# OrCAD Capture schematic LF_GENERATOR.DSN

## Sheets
1 2. description: size A3
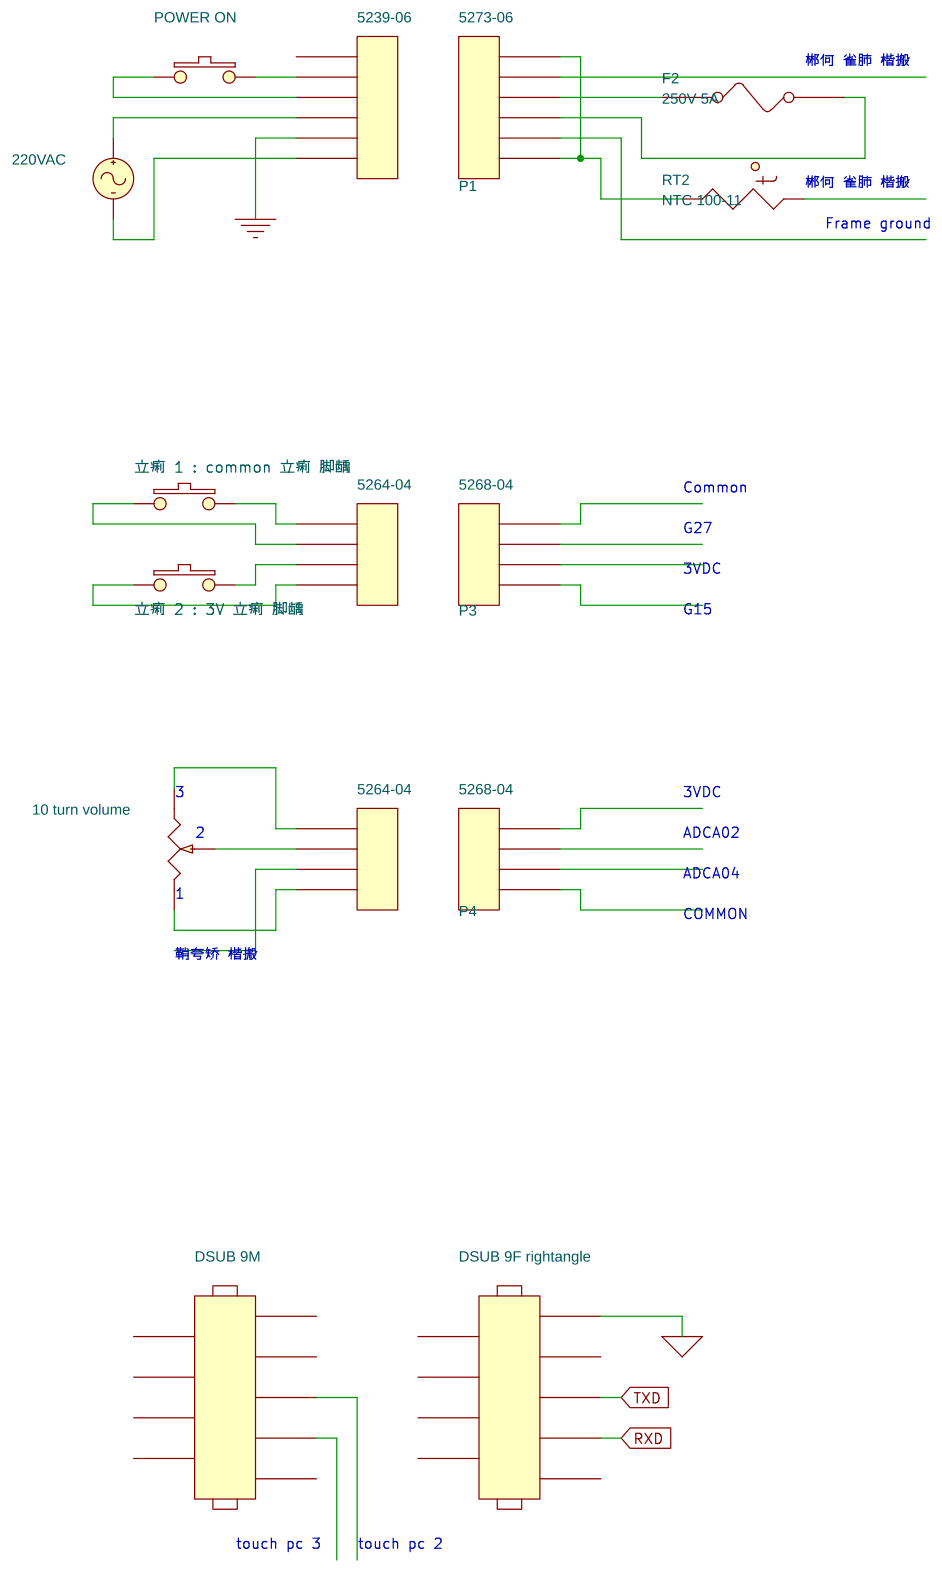
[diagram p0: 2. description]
2 1. Full_Design: size A3; title: LF generator [BELCANTO]; rev: 1.52
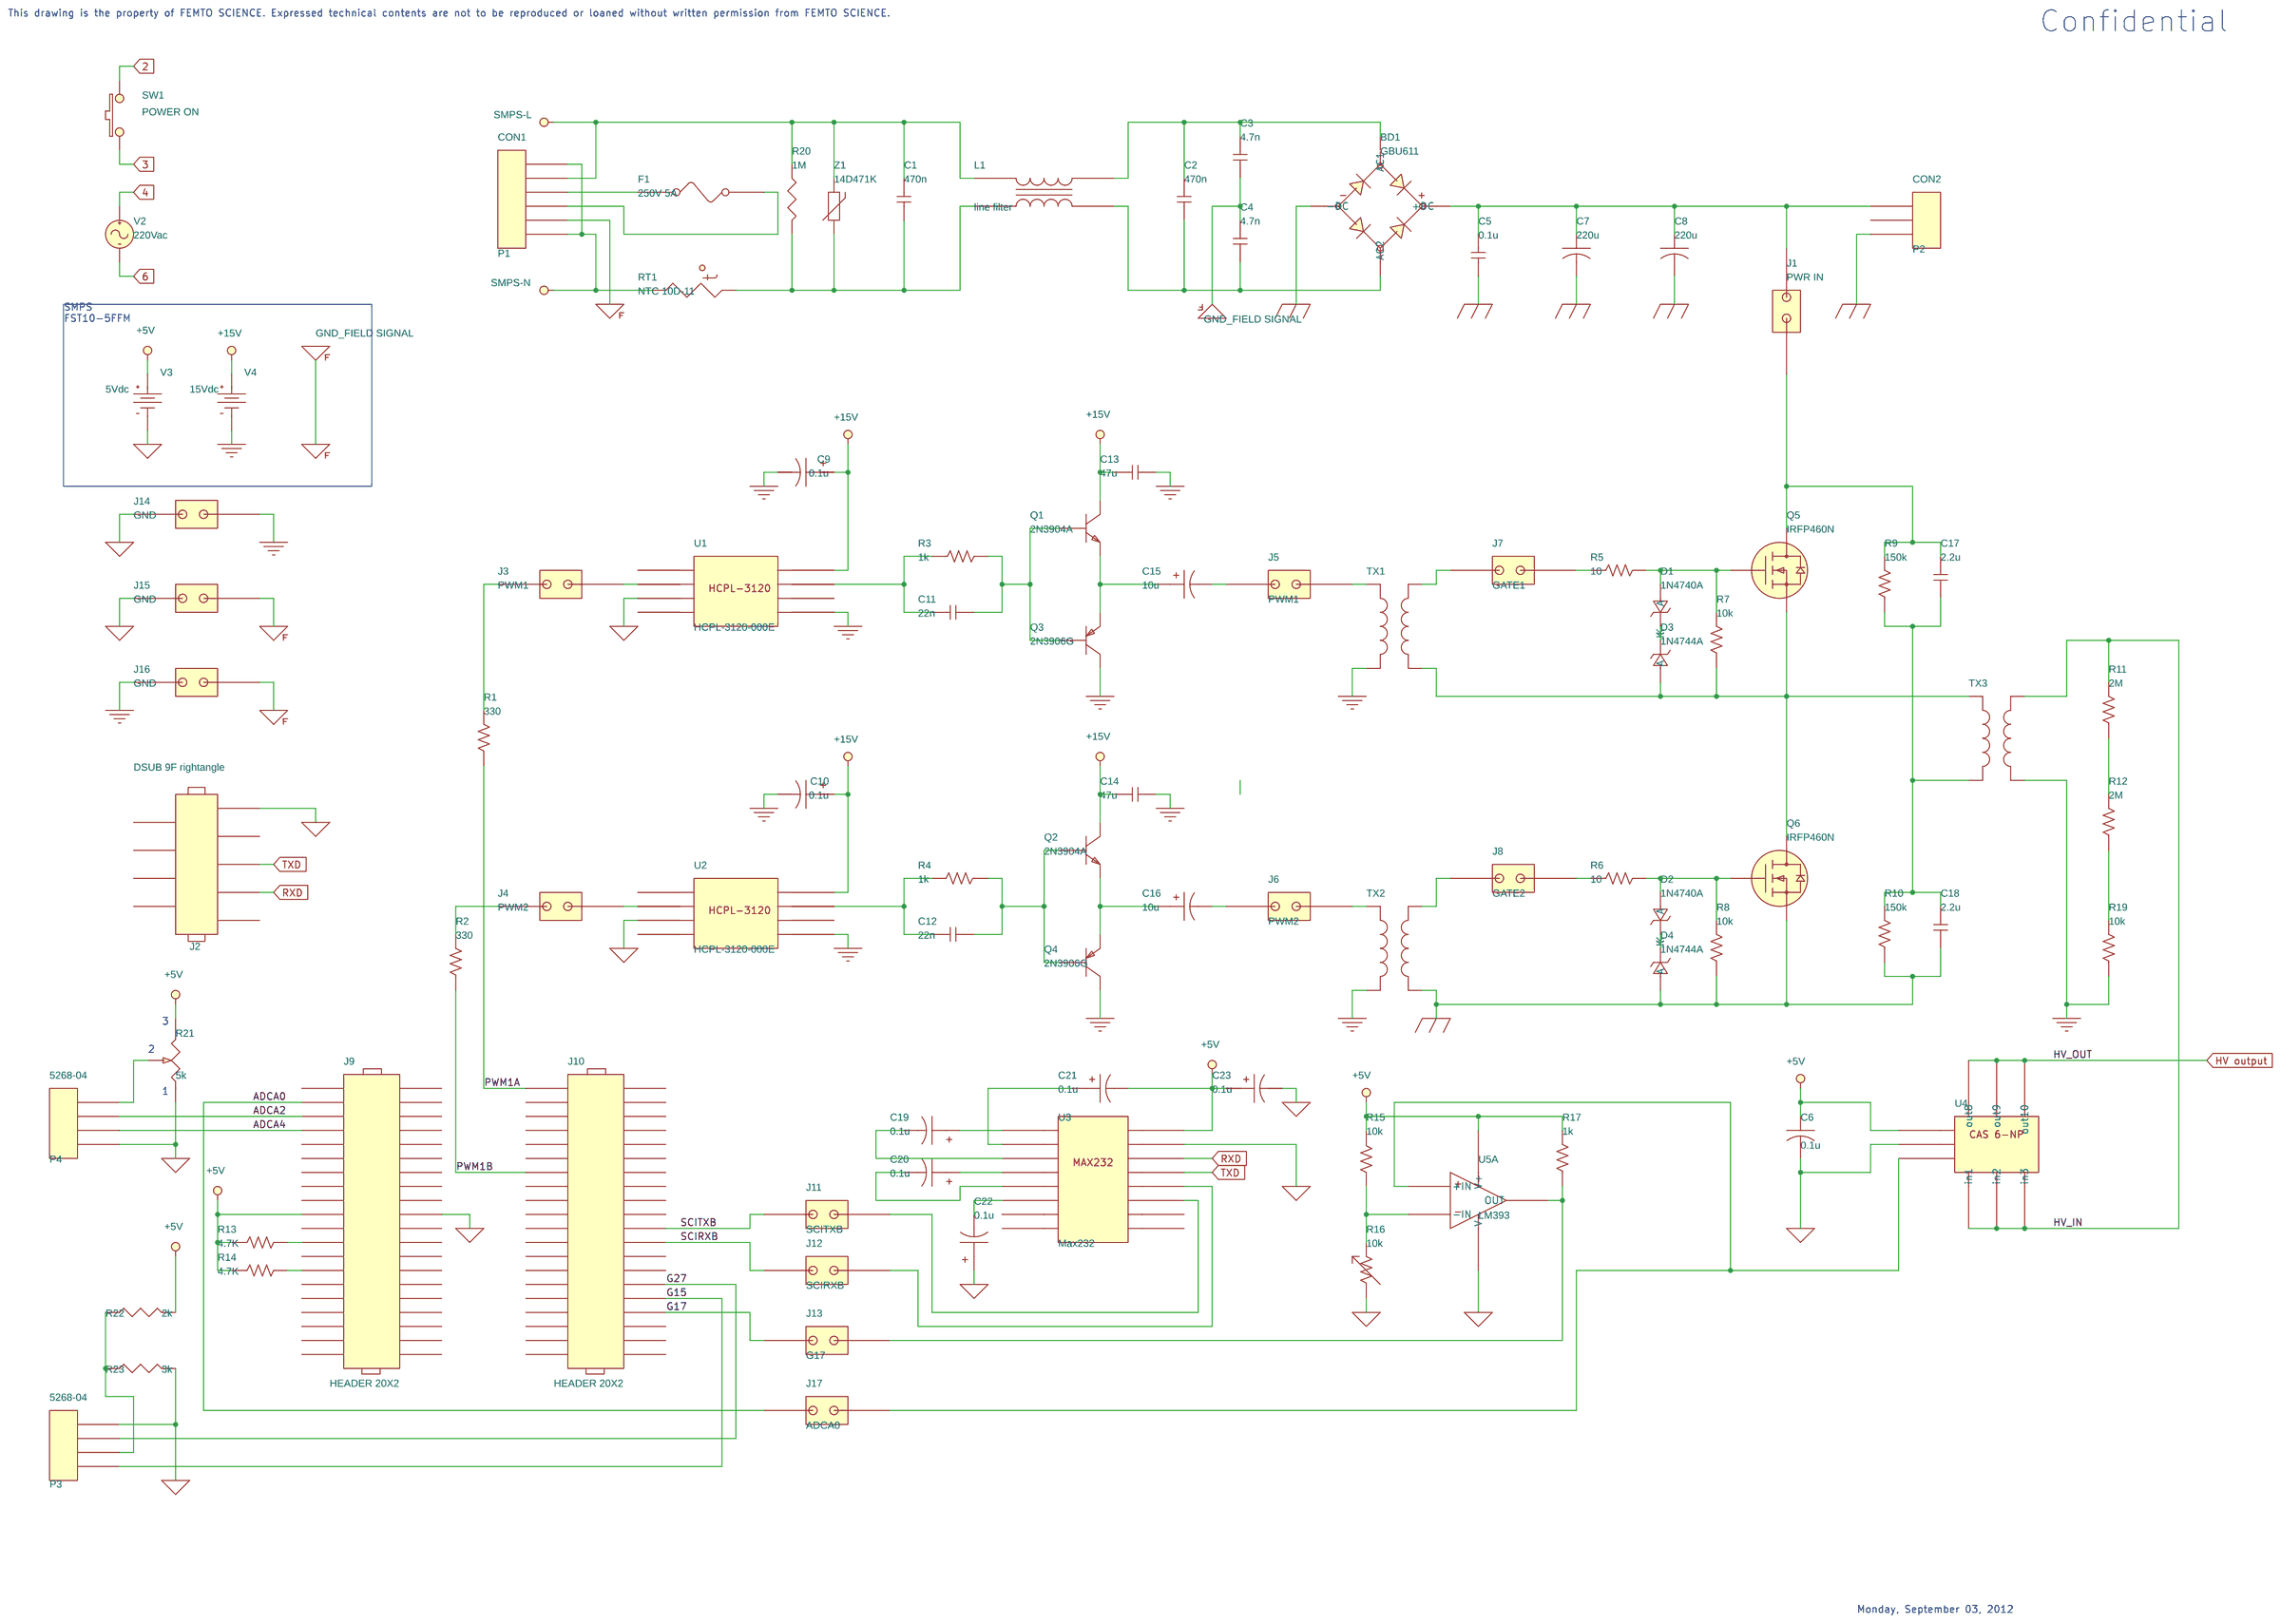
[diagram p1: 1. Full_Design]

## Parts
sheet 1. Full_Design
BD1  GBU611
C1  470n  [RAD/CK05]
C2  470n  [RAD/CK05]
C3  4.7n  [RAD/CK05]
C4  4.7n  [RAD/CK05]
C5  0.1u  [RAD/CK05]
C6  0.1u  [RAD/CK05]
C7  220u  [RAD/CK05]
C8  220u  [RAD/CK05]
C9  0.1u
C10  0.1u
C11  22n  [RAD/CK05]
C12  22n  [RAD/CK05]
C13  47u  [RAD/CK05]
C14  47u  [RAD/CK05]
C15  10u
C16  10u
C17  2.2u  [RAD/CK05]
C18  2.2u  [RAD/CK05]
C19  0.1u
C20  0.1u
C21  0.1u
C22  0.1u
C23  0.1u
D1  1N4740A  [DO-41]
D2  1N4740A  [DO-41]
D3  1N4744A  [DO-41]
D4  1N4744A  [DO-41]
F1  250V 5A
J1  PWR IN
J2  DSUB 9F rightangle
J3  PWM1
J4  PWM2
J5  PWM1
J6  PWM2
J7  GATE1
J8  GATE2
J9  HEADER 20X2
J10  HEADER 20X2
J11  SCITXB
J12  SCIRXB
J13  G17
J14  GND
J15  GND
J16  GND
J17  ADCA0
L1  line filter
P2  CON2
Q1  2N3904A
Q2  2N3904A
Q3  2N3906G
Q4  2N3906G
Q5  IRFP460N  [TO247AC]
Q6  IRFP460N  [TO247AC]
R1  330  [AX/RC05]
R2  330  [AX/RC05]
R3  1k  [AX/RC05]
R4  1k  [AX/RC05]
R5  10  [AX/RC05]
R6  10  [AX/RC05]
R7  10k  [AX/RC05]
R8  10k  [AX/RC05]
R9  150k  [AX/RC05]
R10  150k  [AX/RC05]
R11  2M  [AX/RC05]
R12  2M  [AX/RC05]
R13  4.7K  [AX/RC05]
R14  4.7K  [AX/RC05]
R15  10k  [AX/RC05]
R16  10k  [P1G]
R17  1k  [AX/RC05]
R19  10k  [AX/RC05]
R20  1M  [AX/RC05]
R21  5k
R22  2k  [AX/RC05]
RT1  NTC 10D-11
SW1  POWER ON
TX1  XFRM_LINEAR
TX2  XFRM_LINEAR
TX3  XFRM_LINEAR
U1  HCPL-3120-000E
U2  HCPL-3120-000E
U3  Max232
U4  CAS 6-NP
U5  LM393  (section A)
V2  VAC
V3  VDC
V4  VDC
Z1  14D471K
sheet 2. description
F2  250V 5A
J18  DSUB 9F rightangle
J19  DSUB 9M
J20  5239-06
J21  5264-04
J22  5264-04
P1  5273-06
P1#2  5273-06
P3  5268-04
P3#2  5268-04
P4  5268-04
P4#2  5268-04
R23  10 turn volume
RT2  NTC 100-11
SW2  POWER ON
SW3  立痢 1 : common 立痢 脚龋
SW4  立痢 2 : 3V 立痢 脚龋
V5  VAC

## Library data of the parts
BD1 = BRIDGE_1
C1-C5 C11-C14 C17 C18 = C_v2
C6-C8 = C
C9 C10 C15 C16 C19-C23 = CAP_POL
D1 D2 = 1N4740A
D3 D4 = 1N4744A
F1 F2 = FUSE
J1 J3-J8 J11-J17 = B2S
J2 J18 J19 = CONN_DSUB_9-P
J9 J10 = HEADER_20X2
L1 = CHOKE_CM
P2 = CON3
Q1 Q2 = 2N3904_TO
Q3 Q4 = 2N3906_TO
Q5 Q6 = IRFP460N
R1-R15 R17 R19 = R_v2
R16 = R_var
R20 R22 = R
R21 R23 = RESISTOR_VAR
RT1 RT2 = THERMISTOR
SW1-SW4 = SW_PB_SPST
TX1-TX3 = XFRM_LINEAR
U1 U2 = HCPL-3120
U3 = Max232
U4 = HX_05-P_SP2_2
U5 = LM393
V2 = VAC: ACMAG: 220Vac
V3 = VDC: DC: 5Vdc
V4 = VDC: DC: 15Vdc
Z1 = VARISTOR
J20 P1 P1#2 = CON6
J21 J22 P3 P3#2 P4 P4#2 = CON4
V5 = VAC: ACMAG: 220VAC

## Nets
+5V: C6.1 C21.2 C23.1 J9.19 R13.1 R14.1 R15.1 R17.2 R21.1(A) R22.2 U3.16 U4.11 U5.8(V+) V3.0(+)
+15V: C9.1 C10.1 C13.1 C14.1 Q1.1(C) Q2.1(C) U1.8 U2.8 V4.0(+)
GND EARTH: BD1.2(-DC) C5.1 C7.2 C8.2 C18.1 D4.1(A) P2.3 Q6.3(S) R8.1 R10.1 TX2.4
GND_SIGNAL: C6.2 C22.1 C23.2 J2.5 J9.20 J14.1 J15.1 J18.5 J22.2 P3.1 P4.4 R16.1 R21.3(B) R23.2(WIPER) U1.3 U2.3 U3.15 U4.12 U5.4(V-) V3.1(-)
0: C9.2 C10.2 C13.2 C14.2 J14.2 J16.1 J20.5 Q3.1(C) Q4.1(C) R19.1 TX1.2 TX2.2 TX3.3 U1.5 U2.5 V4.1(-)
2: SW1.2
3: SW1.1
4: V2.1(+)
6: V2.2(-)
ADCA0: J9.3 J17.1
ADCA2: J9.5 P4.2
ADCA4: J9.7 P4.3
FG: C3.1 C4.2 J15.2 J16.2 P1.5
G15: J10.32 P3.4
G17: J10.34 J13.1
G27: J10.30 P3.2
HV output: U4.8(out8) U4.9(out9) U4.10(out10)
HV_IN: R11.2 TX3.4 U4.1(in1) U4.2(in2) U4.3(in3)
PWM1A: J10.1 R1.1
PWM1B: J10.13 R2.1
RXD: J2.2 J18.2 U3.14
SCIRXB: J10.24 J12.1
SCITXB: J10.22 J11.1
SMPS-L: C1.2 L1.1 P1.2 R20.1 Z1.2
SMPS-N: P1.1 P1.6 RT1.1
TXD: J2.3 J18.3 U3.13
N143697: J17.2 U4.13 U5.3(+IN)
N143735: R15.2 R16.2 U5.2(-IN)
N143831: J13.2 R17.1 U5.1(OUT)
N143981: C20.2 U3.5
N144041: C19.1 U3.1
N144045: C19.2 U3.3
N144301: F1.1 P1.3
N144321: F1.2 P1.4
N144437: C1.1 L1.2 R20.2 RT1.2 Z1.1
N144497: BD1.1(AC1) C2.2 C3.2 L1.3
N144501: BD1.3(AC2) C2.1 C4.1 L1.4
N144701: J11.2 U3.11
N144725: BD1.4(+DC) C5.2 C7.1 C8.1 J1.1 P2.1
N144991: C17.2 J1.2 Q5.2(D) R9.2
N145003: D3.1(A) Q5.3(S) Q6.2(D) R7.1 TX1.4 TX3.2
N145007: C17.1 C18.2 R9.1 R10.2 TX3.1
N145019: D1.1(A) Q5.1(G) R5.2 R7.2
N145095: D2.1(A) Q6.1(G) R6.2 R8.2
N145227: D1.2(K) D3.2(K)
N145283: D2.2(K) D4.2(K)
N145677: C15.2 J5.1
N145681: J5.2 TX1.1
N145689: C16.2 J6.1
N145709: J6.2 TX2.1
N145753: J3.2 U1.2
N145757: J3.1 R1.2
N145765: J4.2 U2.2
N145785: J4.1 R2.2
N145935: J7.1 TX1.3
N145943: J8.1 TX2.3
N146005: C11.2 Q1.2(B) Q3.2(B) R3.2
N146135: C15.1 Q1.3(E) Q3.3(E)
N146187: C11.1 R3.1 U1.7
N146243: J7.2 R5.1
N146267: J8.2 R6.1
N146435: J9.27 R14.2
N146477: J9.23 R13.2
N146541: J12.2 U3.12
N146621: C12.2 Q2.2(B) Q4.2(B) R4.1
N146669: C16.1 Q2.3(E) Q4.3(E)
N146705: C12.1 R4.2 U2.7
N146817: C22.2 U3.6
N146929: C20.1 U3.4
N146933: C21.1 U3.2
N147077: R11.1 R12.2
N147141: R12.1 R19.2
N149290: F2.1 P1#2.3
N149310: F2.2 P1#2.4
N149402: P1#2.1 P1#2.6 RT2.1
N149840: J20.2 SW2.2
N149844: J20.3 SW2.1
N149908: J20.4 V5.1(+)
N149915: J20.6 V5.2(-)
N156416: J21.1 SW3.2
N156428: J21.2 SW3.1
N156447: J21.3 SW4.2
N156457: J21.4 SW4.1
N157484: J22.1 P3.3 R22.1 R23.1(A)
N157510: J22.4 R23.3(B)
N169389: P4.1 R21.2(WIPER)

Not connected (* = marked no-connect by the designer): J2 1 4 6 7 8 9; J9 1 2 4 6 8 9 10 11 12 13 14 15 16 17 18 21 22 24 25 26 28 29 30 31 32 33 34 35 36 37 38 39 40; J10 2 3 4 5 6 7 8 9 10 11 12 14 15 16 17 18 19 20 21 23 25 26 27 28 29 31 33 35 36 37 38 39 40; J18 1 4 6 7 8 9; J19 1 2 3 4 5 6 7 8 9; J20 1; J22 3; P1#2 2 5; P2 2; P3#2 1 2 3 4; P4#2 1 2 3 4; RT2 2; U1 1 4 6; U2 1 4 6; U3 7 8 9 10

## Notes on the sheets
sheet 1
- 郴何 雀肺 楷搬
- 郴何 雀肺 楷搬
- Frame ground
- Common
- G27
- 3VDC
- G15
- 3
- 3VDC
- 2
- ADCA02
- ADCA04
- 1
- COMMON
- 鞘夸矫 楷搬
- touch pc 3
- touch pc 2
sheet 2
- This drawing is the property of FEMTO SCIENCE. Expressed technical contents are not to be reproduced or loaned without written permission from FEMTO SCIENCE.
- Confidential
- SMPS
  FST10-5FFM
- 3
- 2
- 1
- Monday, September 03, 2012
